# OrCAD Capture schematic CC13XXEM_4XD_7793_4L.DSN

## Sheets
1 CC13xxEM_4XD_7793_4L: size A3; title: CC13xxEM-4XD-7793_4L; rev: 1.0.0
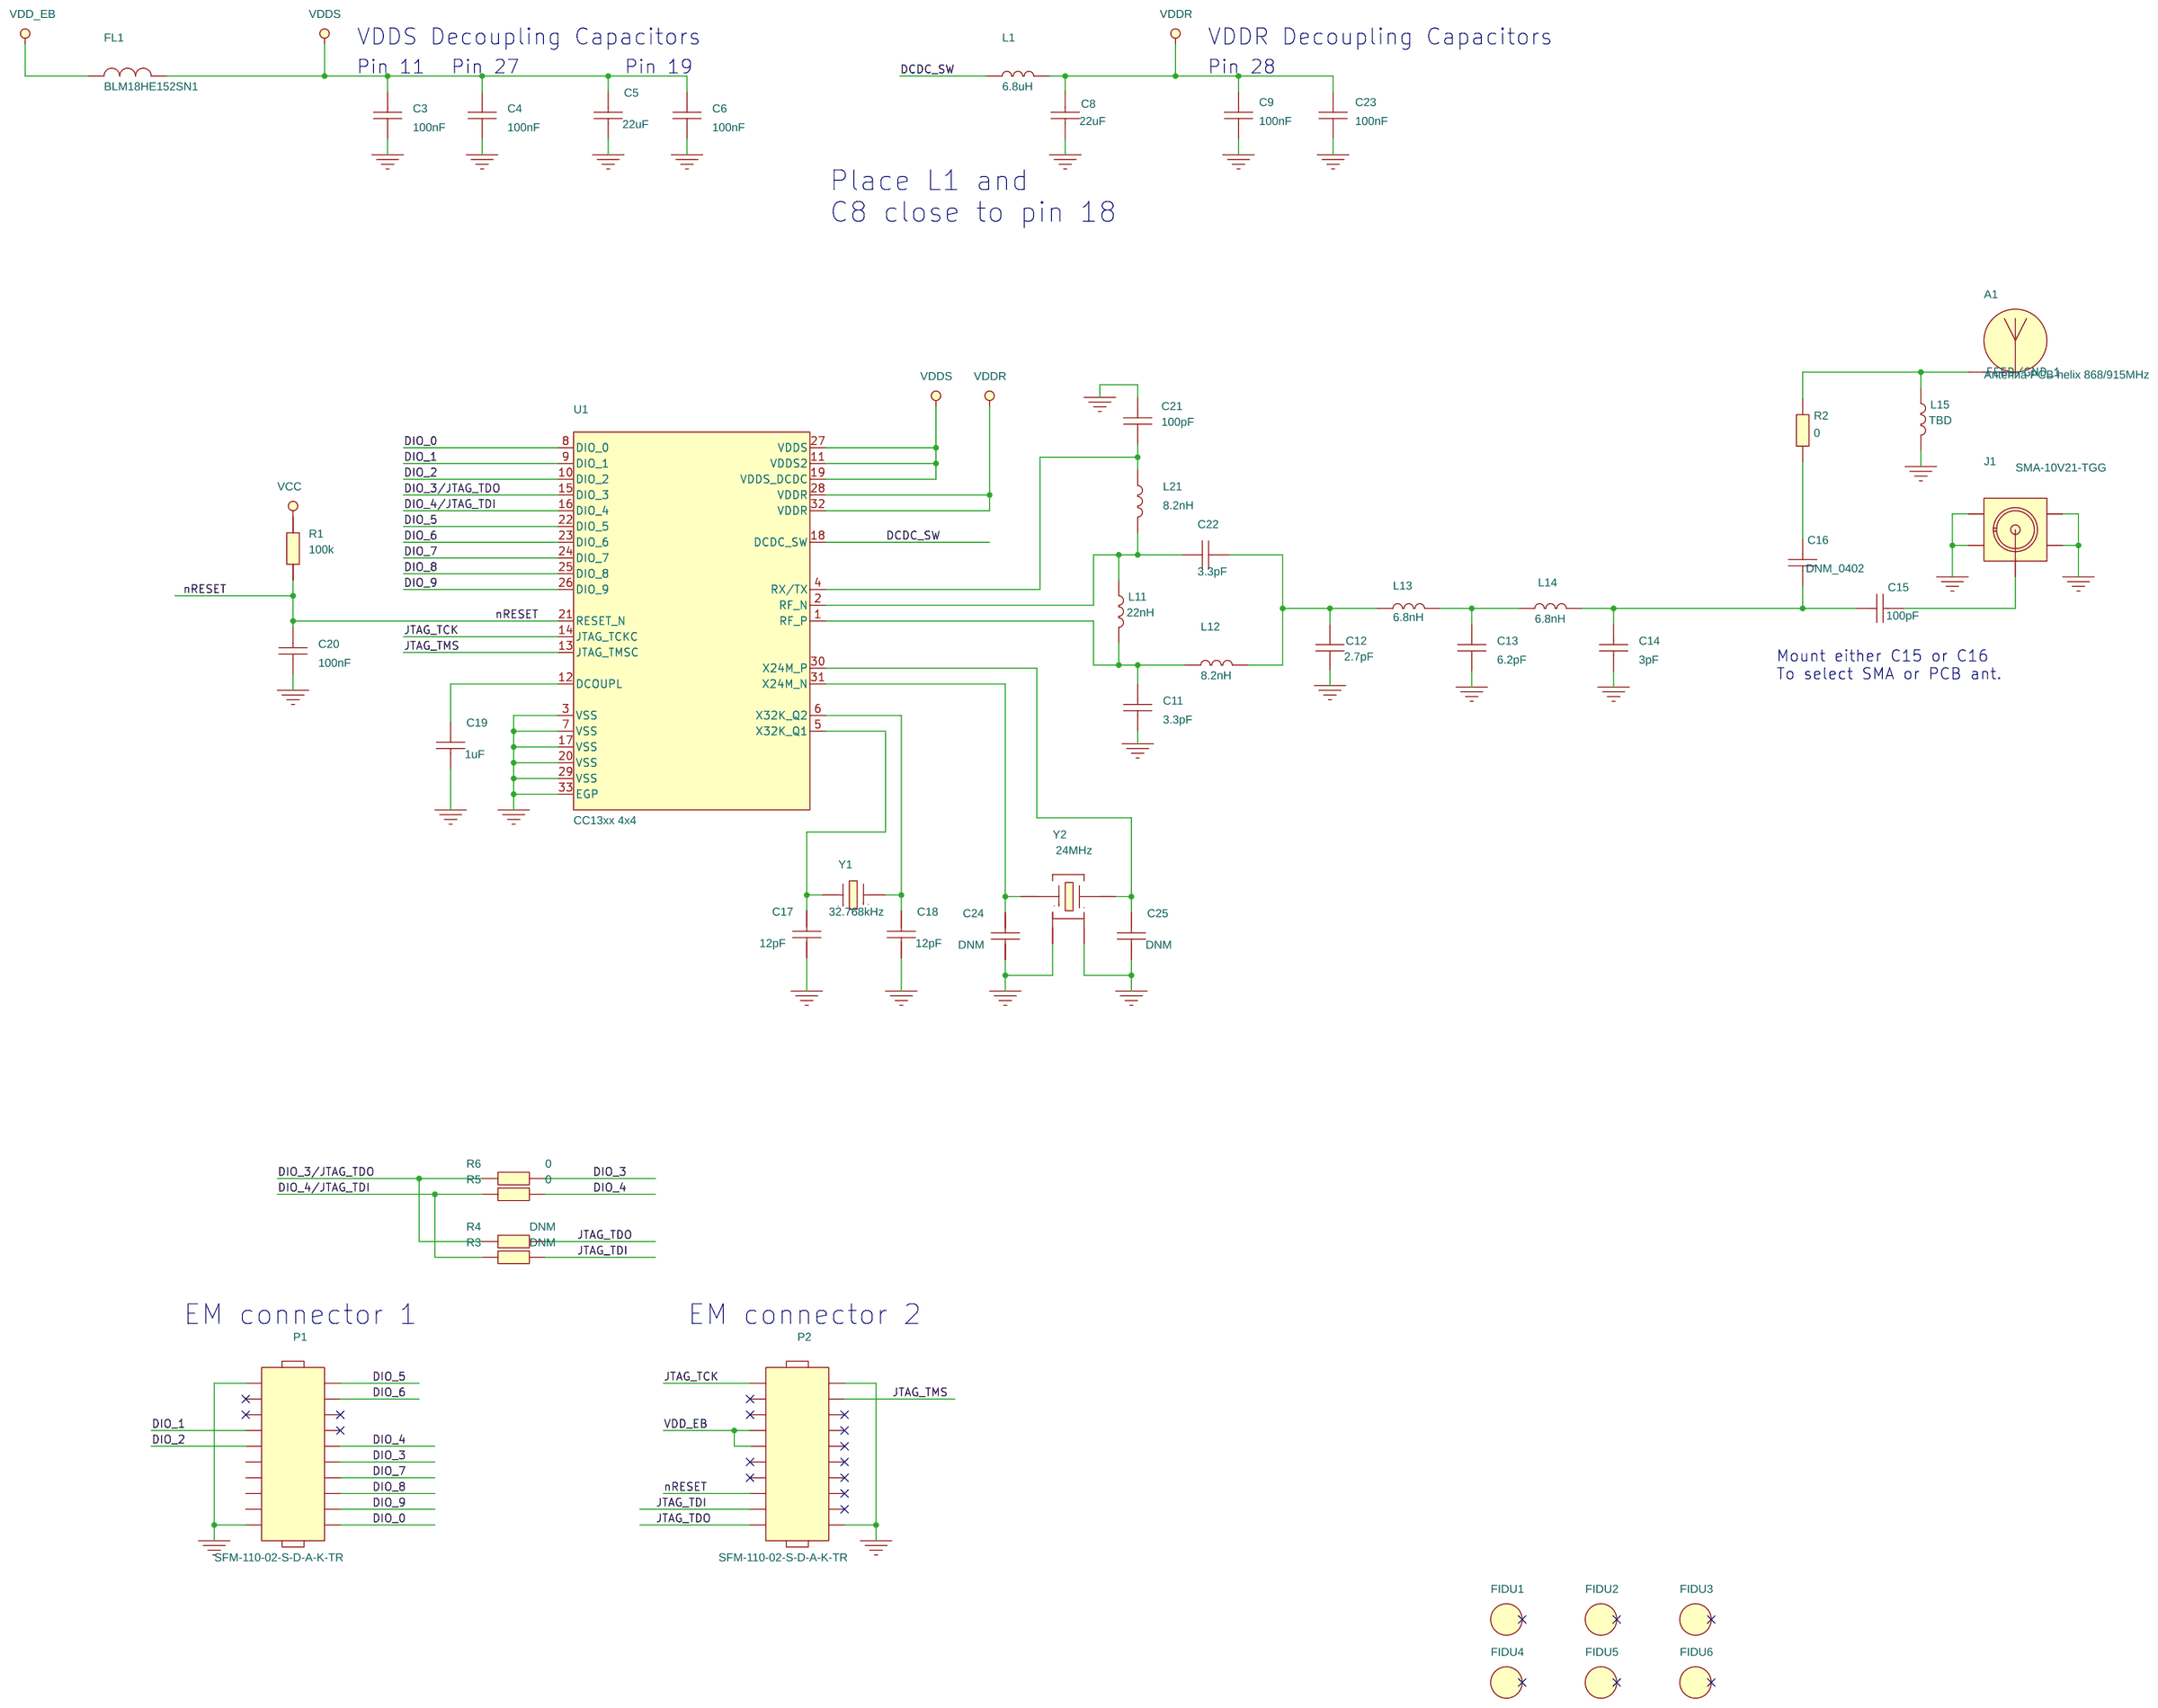
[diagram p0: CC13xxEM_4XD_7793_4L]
2 Revision: title: Revision
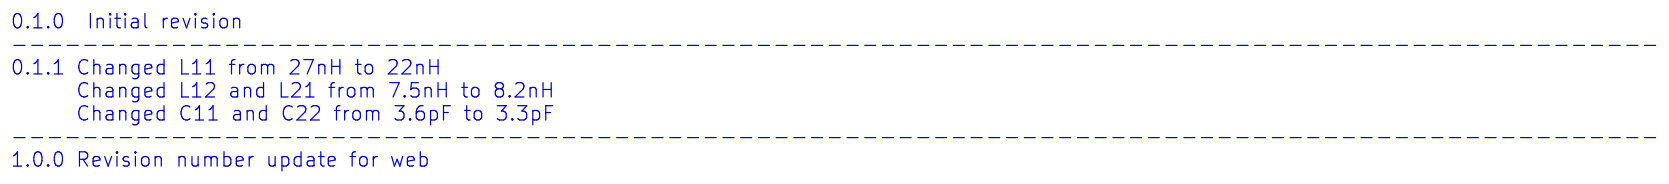
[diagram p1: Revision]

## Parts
A1  Antenna PCB helix 868/915MHz  [Antenna868_915MHz_MIRROR_A2N]
C3  100nF  [CAPC1005X60L]
C4  100nF  [CAPC1005X60L]
C5  22uF  [CAPC1608X100A2L]
C6  100nF  [CAPC1005X60L]
C8  22uF  [CAPC1608X100A2L]
C9  100nF  [CAPC1005X60L]
C11  3.3pF  [CAPC1005X60L]
C12  2.7pF  [CAPC1005X60L]
C13  6.2pF  [CAPC1005X60L]
C14  3pF  [CAPC1005X60L]
C15  100pF  [CAPC1005X60N]
C16  DNM_0402  [CAPC1005X60N]
C17  12pF  [CAPC1005X60L]
C18  12pF  [CAPC1005X60L]
C19  1uF  [CAPC1005X60L]
C20  100nF  [CAPC1005X60L]
C21  100pF  [CAPC1005X60L]
C22  3.3pF  [CAPC1005X60L]
C23  100nF  [CAPC1005X60L]
C24  DNM  [CAPC1005X60L]
C25  DNM  [CAPC1005X60L]
FIDU1  FIDU_1MM  [FID100X115]
FIDU2  FIDU_1MM  [FID100X115]
FIDU3  FIDU_1MM  [FID100X115]
FIDU4  FIDU_1MM  [FID100X115]
FIDU5  FIDU_1MM  [FID100X115]
FIDU6  FIDU_1MM  [FID100X115]
FL1  BLM18HE152SN1  [FIL_BLM18HE152SN1DL]
J1  SMA-10V21-TGG  [HUSTSAN_SMA10V21TGGAN]
L1  6.8uH  [INDC2012X150L]
L11  22nH  [INDC1005X60L]
L12  8.2nH  [INDC1005X60L]
L13  6.8nH  [INDC1005X60L]
L14  6.8nH  [INDC1005X60L]
L15  TBD  [INDC1005X60L]
L21  8.2nH  [INDC1005X60L]
P1  SFM-110-02-S-D-A-K-TR  [SAMTEC_SFM11002AN]
P2  SFM-110-02-S-D-A-K-TR  [SAMTEC_SFM11002AN]
R1  100k  [RESC1005X40L]
R2  0  [RESC1005X40L]
R3  DNM  [RESC1005X40L]
R4  DNM  [RESC1005X40L]
R5  0  [RESC1005X40N]
R6  0  [RESC1005X40N]
U1  CC13xx 4x4  [QFNFC40P400X400X100-33L]
Y1  32.768kHz  [XTAL_FC-135N]
Y2  24MHz  [OSCCC250X320X80-4L]

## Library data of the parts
A1 = ANTENNA: ANTENNA, NON COMPONENT, PCB HELIX 868/915MHz, NOT APPLY; AutoDoc File: http://notefied-dynamic-precision.com/DB/Apps/Desktop/Item/Object.aspx?id=87165; Budget Currency: N/A; Budget Price: N/A; Datasheet URL 1: N/A; Datasheet URL 2: www.ti.com; Definied Quality: COMMERCIAL; Esd Level: N/A; FPLIST: Antenna868_915MHz_A2N,Antenna868_915MHz_MIRROR_A2N,; Frequency: 868/915MHz; Last Time Buy: N/A; Lead Time: N/A; LifeCycle Status: ACTIVE; MPN: ANTENNA PCB HELIX 868/915MHz; MPN Status: ACTIVE; MSL: N/A; MTBF: N/A; MTBF Standard: N/A; Manufacturer: TEXAS INSTRUMENTS; Max Oper Temp: N/A; Min Oper Temp: N/A; Mounting Type: NOT APPLY; NOTE Status: PREFERRED; Old Footprint: Antenna868_915MHz_A2N,Antenna868_915MHz_MIRROR_A2N; Packing Size: 2500; Packing Type: TAPE_&_REEL; Part Number: 13-00397; Part Type: MECHANIC\ANTENNA\NON_COMPONENT; Revision: R003; RoHS Status: ROHS_COMPLIANT; WEIGHT: N/A
C3 C4 C6 C9 C23 = CAPACITOR: CAPACITOR, CERAMIC X7R, 100nF, 6.3V, -10%/+10%, -55DEGC/+125DEGC, 0402, SMD; ALT_SYMBOLS: CAPC1005X60L,CAPC1005X60M; AutoDoc File: http://notefied-dynamic-precision.com/DB/Apps/Desktop/Item/Object.aspx?id=73748; Budget Currency: EUR; Budget Price: 0.007; Datasheet URL 1: http://search.murata.co.jp/Ceramy/image/img/w_hinm/L0005E.pdf; Datasheet URL 2: http://psearch.murata.com/capacitor/product/GRM155R70J104KA01%23.pdf; Definied Quality: INDUSTRIAL; Dielectric Type: X7R; Esd Level: N/A; FPLIST: CAPC1005X60N,CAPC1005X60L,CAPC1005X60M; Last Time Buy: N/A; Lead Time: 14; LifeCycle Status: NRND; MPN: GRM155R70J104KA01D; MPN Status: NRND; MSL: 1; MTBF: N/A; MTBF Standard: N/A; Manufacturer: MURATA; Max Oper Temp: +125DEGC; Max Tol: +10%; Min Oper Temp: -55DEGC; Min Tol: -10%; Mounting Type: SMD; NOTE Status: PREFERRED; Old Footprint: CAPC1005X60N,0402; PCB Package: 0402; Packing Size: 10000; Packing Type: TAPE_&_REEL; Part Number: 02-02323; Part Type: CAPACITOR\CERAMIC\0402; Revision: R000; RoHS Status: ROHS_COMPLIANT; Rtd Voltage: 6.3V; WEIGHT: 0.0016g
C5 C8 = CAPACITOR: CAPACITOR, CERAMIC, X5R, 22uF, 6.3V, -20%/+20%, -55DEGC/+85DEGC, 0603, SMD; ALT_SYMBOLS: CAPC1608X100A2L,CAPC1608X100A2M; AutoDoc File: http://notefied-dynamic-precision.com/DB/Apps/Desktop/Item/Object.aspx?id=104385; Budget Currency: EUR; Budget Price: 0.062; Datasheet URL 1: N/A; Datasheet URL 2: http://psearch.murata.com/capacitor/product/GRM188R60J226MEA0%23.pdf; Definied Quality: INDUSTRIAL; Dielectric Type: X5R; Esd Level: N/A; FPLIST: CAPC1608X100A2N,CAPC1608X100A2L,CAPC1608X100A2M; Last Time Buy: N/A; Lead Time: 26; LifeCycle Status: ACTIVE; MPN: GRM188R60J226MEA0D; MPN Status: ACTIVE; MSL: N/A; MTBF: N/A; MTBF Standard: N/A; Manufacturer: MURATA; Max Oper Temp: +85DEGC; Max Tol: +20%; Min Oper Temp: -55DEGC; Min Tol: -20%; Mounting Type: SMD; NOTE Status: PREFERRED; Old Footprint: CAPC1608X100A2N; PCB Package: 0603; Packing Size: 4000; Packing Type: TAPE_&_REEL; Part Number: 02-07053; Part Type: CAPACITOR\CERAMIC\0603; Revision: R001; RoHS Status: ROHS_COMPLIANT; Rtd Voltage: 6.3V; WEIGHT: 0.0091g
C11 C22 = CAPACITOR: CAPACITOR, CERAMIC C0G/NP0, 3.3pF, 50V, -0.25pF/+0.25pF, -55DEGC/+125DEGC, 0402, SMD; ALT_SYMBOLS: CAPC1005X60L,CAPC1005X60M; AutoDoc File: http://notefied-dynamic-precision.com/DB/Apps/Desktop/Item/Object.aspx?id=86077; Budget Currency: EUR; Budget Price: 0.007; Datasheet URL 1: http://search.murata.co.jp/Ceramy/image/img/w_hinm/L0005E.pdf; Datasheet URL 2: http://psearch.murata.com/capacitor/product/GRM1555C1H3R3CA01%23.pdf; Definied Quality: INDUSTRIAL; Dielectric Type: C0G/NP0; Esd Level: N/A; FPLIST: CAPC1005X60N,CAPC1005X60L,CAPC1005X60M; Last Time Buy: N/A; Lead Time: 12; LifeCycle Status: ACTIVE; MPN: GRM1555C1H3R3CA01D; MPN Status: ACTIVE; MSL: 1; MTBF: N/A; MTBF Standard: N/A; Manufacturer: MURATA; Max Oper Temp: +125DEGC; Max TC: +30PPM/DEGC; Max Tol: +0.25pF; Min Oper Temp: -55DEGC; Min TC: -30PPM/DEGC; Min Tol: -0.25pF; Mounting Type: SMD; NOTE Status: PREFERRED; Old Footprint: CAPC1005X60N; PCB Package: 0402; Packing Size: 10000; Packing Type: TAPE_&_REEL; Part Number: 02-04369; Part Type: CAPACITOR\CERAMIC\0402; Revision: R001; RoHS Status: ROHS_COMPLIANT; Rtd Voltage: 50V; WEIGHT: 0.0016g
C12 = CAPACITOR: CAPACITOR, CERAMIC C0G/NP0, 2.7pF, 50V, -0.25pF/+0.25pF, -55DEGC/+125DEGC, 0402, SMD; ALT_SYMBOLS: CAPC1005X60L,CAPC1005X60M; AutoDoc File: http://notefied-dynamic-precision.com/DB/Apps/Desktop/Item/Object.aspx?id=87809; Budget Currency: EUR; Budget Price: 0.006; Datasheet URL 1: http://search.murata.co.jp/Ceramy/image/img/w_hinm/L0005E.pdf; Datasheet URL 2: http://psearch.murata.com/capacitor/product/GRM1555C1H2R7CA01%23.pdf; Definied Quality: INDUSTRIAL; Dielectric Type: C0G/NP0; Esd Level: N/A; FPLIST: CAPC1005X60N,CAPC1005X60L,CAPC1005X60M; Last Time Buy: N/A; Lead Time: 12; MPN: GRM1555C1H2R7CA01D; MPN Status: ACTIVE; MSL: 1; MTBF: N/A; MTBF Standard: N/A; Manufacturer: MURATA; Max Oper Temp: +125DEGC; Max Tol: +0.25pF; Min Oper Temp: -55DEGC; Min Tol: -0.25pF; Mounting Type: SMD; NOTE Status: PREFERRED; Old Footprint: CAPC1005X60N; PCB Package: 0402; Packing Size: 10000; Packing Type: TAPE_&_REEL; Part Number: 02-04679; Part Type: CAPACITOR\CERAMIC\0402; Revision: R001; RoHS Status: ROHS_COMPLIANT; Rtd Voltage: 50V; WEIGHT: 0.0016g
C13 = CAPACITOR: CAPACITOR, CERAMIC C0G/NP0, 6.2pF, 50V, -0.25pF/+0.25pF, -55DEGC/+125DEGC, 0402, SMD; ALT_SYMBOLS: CAPC1005X60L,CAPC1005X60M; AutoDoc File: http://notefied-dynamic-precision.com/DB/Apps/Desktop/Item/Object.aspx?id=87255; Budget Currency: EUR; Budget Price: 0.006; Datasheet URL 1: http://search.murata.co.jp/Ceramy/image/img/w_hinm/L0005E.pdf; Datasheet URL 2: http://psearch.murata.com/capacitor/product/GRM1555C1H6R2CA01%23.pdf; Definied Quality: INDUSTRIAL; Dielectric Type: C0G/NP0; Esd Level: N/A; FPLIST: CAPC1005X60N,CAPC1005X60L,CAPC1005X60M; Last Time Buy: N/A; Lead Time: 10; MPN: GRM1555C1H6R2CA01D; MPN Status: ACTIVE; MSL: 1; MTBF: N/A; MTBF Standard: N/A; Manufacturer: MURATA; Max Oper Temp: +125DEGC; Max Tol: +0.25pF; Min Oper Temp: -55DEGC; Min Tol: -0.25pF; Mounting Type: SMD; NOTE Status: PREFERRED; Old Footprint: CAPC1005X60N; PCB Package: 0402; Packing Size: 10000; Packing Type: TAPE_&_REEL; Part Number: 02-04608; Part Type: CAPACITOR\CERAMIC\0402; Revision: R001; RoHS Status: ROHS_COMPLIANT; Rtd Voltage: 50V; WEIGHT: 0.0016g
C14 = CAPACITOR: CAPACITOR, CERAMIC C0G/NP0, 3pF, 50V, -0.25pF/+0.25pF, -55DEGC/+125DEGC, 0402, SMD; ALT_SYMBOLS: CAPC1005X60L,CAPC1005X60M; AutoDoc File: http://notefied-dynamic-precision.com/DB/Apps/Desktop/Item/Object.aspx?id=87252; Budget Currency: EUR; Budget Price: 0.006; Datasheet URL 1: http://search.murata.co.jp/Ceramy/image/img/w_hinm/L0005E.pdf; Datasheet URL 2: http://psearch.murata.com/capacitor/product/GRM1555C1H3R0CA01%23.pdf; Definied Quality: INDUSTRIAL; Dielectric Type: C0G/NP0; Esd Level: N/A; FPLIST: CAPC1005X60N,CAPC1005X60L,CAPC1005X60M; Last Time Buy: N/A; Lead Time: 16; LifeCycle Status: ACTIVE; MPN: GRM1555C1H3R0CA01D; MPN Status: ACTIVE; MSL: 1; MTBF: N/A; MTBF Standard: N/A; Manufacturer: MURATA; Max Oper Temp: +125DEGC; Max Tol: +0.25pF; Min Oper Temp: -55DEGC; Min Tol: -0.25pF; Mounting Type: SMD; NOTE Status: PREFERRED; Old Footprint: CAPC1005X60N; PCB Package: 0402; Packing Size: 10000; Packing Type: TAPE_&_REEL; Part Number: 02-04606; Part Type: CAPACITOR\CERAMIC\0402; Revision: R001; RoHS Status: ROHS_COMPLIANT; Rtd Voltage: 50V; WEIGHT: 0.0016g
C15 = CAPACITOR: CAPACITOR, CERAMIC C0G/NP0, 100pF, 50V, -5%/+5%, -55DEGC/+125DEGC, 0402, SMD; ALT_SYMBOLS: CAPC1005X60L,CAPC1005X60M; AutoDoc File: http://notefied-dynamic-precision.com/DB/Apps/Desktop/Item/Object.aspx?id=86072; Budget Currency: EUR; Budget Price: 0.004; Datasheet URL 1: http://search.murata.co.jp/Ceramy/image/img/w_hinm/L0005E.pdf; Datasheet URL 2: http://psearch.murata.com/capacitor/product/GRM1555C1H101JA01%23.pdf; Definied Quality: INDUSTRIAL; Dielectric Type: C0G/NP0; Esd Level: N/A; FPLIST: CAPC1005X60N,CAPC1005X60L,CAPC1005X60M; Last Time Buy: N/A; Lead Time: 12; LifeCycle Status: ACTIVE; MPN: GRM1555C1H101JA01D; MPN Status: ACTIVE; MSL: 1; MTBF: N/A; MTBF Standard: N/A; Manufacturer: MURATA; Max Oper Temp: +125DEGC; Max Tol: +5%; Min Oper Temp: -55DEGC; Min Tol: -5%; Mounting Type: SMD; NOTE Status: PREFERRED; PCB Package: 0402; Packing Size: 10000; Packing Type: TAPE_&_REEL; Part Number: 02-04365; Part Type: CAPACITOR\CERAMIC\0402; Revision: R002; RoHS Status: ROHS_COMPLIANT; Rtd Voltage: 50V; WEIGHT: 0.0016g
C16 = CAPACITOR: CAPACITOR, CERAMIC, N/A VALUE, -55DEGC/+125DEGC, 0402, SMD; ALT_SYMBOLS: CAPC1005X60L,CAPC1005X60M; AutoDoc File: http://notefied-dynamic-precision.com/DB/Apps/Desktop/Item/Object.aspx?id=84862; Budget Currency: USD; Budget Price: 0.00589; Datasheet URL 1: N/A; Datasheet URL 2: N/A; Definied Quality: INDUSTRIAL; Esd Level: N/A; FPLIST: CAPC1005X60N,CAPC1005X60L,CAPC1005X60M; Last Time Buy: N/A; Lead Time: N/A; LifeCycle Status: ACTIVE; MPN: CAPACITOR_0402_DNM_N/A_M; MPN Status: ACTIVE; MSL: N/A; MTBF: N/A; MTBF Standard: N/A; Manufacturer: MANUFACTURER SELECTION; Max Oper Temp: +125DEGC; Min Oper Temp: -55DEGC; Mounting Type: SMD; NOTE Status: PREFERRED; PCB Package: 0402; Packing Size: 10000; Packing Type: TAPE_&_REEL; Part Number: 02-04164; Part Type: CAPACITOR\CERAMIC\0402; Revision: R000; RoHS Status: MISSING_INFO; WEIGHT: N/A
C17 C18 = CAPACITOR: CAPACITOR, CERAMIC C0G/NP0, 12pF, 50V, -5%/+5%, -55DEGC/+125DEGC, 0402, SMD; ALT_SYMBOLS: CAPC1005X60L,CAPC1005X60M; AutoDoc File: http://notefied-dynamic-precision.com/DB/Apps/Desktop/Item/Object.aspx?id=80123; Budget Currency: USD; Budget Price: 0.00589; Datasheet URL 1: N/A; Datasheet URL 2: N/A; Definied Quality: INDUSTRIAL; Dielectric Type: C0G/NP0; Esd Level: N/A; FPLIST: CAPC1005X60N,CAPC1005X60L,CAPC1005X60M; Last Time Buy: N/A; Lead Time: N/A; LifeCycle Status: ACTIVE; MPN: CAPACITOR_0402_12pF_C0G/NP0_M_+/-5%_50V; MPN Status: ACTIVE; MSL: N/A; MTBF: N/A; MTBF Standard: N/A; Manufacturer: MANUFACTURER SELECTION; Max Oper Temp: +125DEGC; Max Tol: +5%; Min Oper Temp: -55DEGC; Min Tol: -5%; Mounting Type: SMD; NOTE Status: PREFERRED; Old Footprint: CAPC1005X60N; PCB Package: 0402; Packing Size: 10000; Packing Type: TAPE_&_REEL; Part Number: 02-03030; Part Type: CAPACITOR\CERAMIC\0402; Revision: R000; RoHS Status: ROHS_COMPLIANT; Rtd Voltage: 50V; WEIGHT: N/A
C19 = CAPACITOR: CAPACITOR, CERAMIC X5R, 1uF, 10V, -10%/+10%, -55DEGC/+85DEGC, 0402, SMD; ALT_SYMBOLS: CAPC1005X60L,CAPC1005X60M; AutoDoc File: http://notefied-dynamic-precision.com/DB/Apps/Desktop/Item/Object.aspx?id=74236; Budget Currency: EUR; Budget Price: 0.015; Datasheet URL 1: http://search.murata.co.jp/Ceramy/image/img/w_hinm/L0005E.pdf; Datasheet URL 2: http://psearch.murata.com/capacitor/product/GRM155R61A105KE15%23.pdf; Definied Quality: INDUSTRIAL; Dielectric Type: X5R; Esd Level: N/A; FPLIST: CAPC1005X60N,CAPC1005X60L,CAPC1005X60M; Last Time Buy: N/A; Lead Time: 14; MPN: GRM155R61A105KE15D; MPN Status: ACTIVE; MSL: 1; MTBF: N/A; MTBF Standard: N/A; Manufacturer: MURATA; Max Oper Temp: +85DEGC; Max Tol: +10%; Min Oper Temp: -55DEGC; Min Tol: -10%; Mounting Type: SMD; NOTE Status: PREFERRED; Old Footprint: CAPC1005X60N,0402; PCB Package: 0402; Packing Size: 10000; Packing Type: TAPE_&_REEL; Part Number: 02-02381; Part Type: CAPACITOR\CERAMIC\0402; Revision: R002; RoHS Status: ROHS_COMPLIANT; Rtd Voltage: 10V; WEIGHT: 0.0016g
C20 = CAPACITOR: CAPACITOR, CERAMIC X7R, 100nF, 6.3V, -10%/+10%, -55DEGC/+125DEGC, 0402, SMD; ALT_SYMBOLS: CAPC1005X60L,CAPC1005X60M; AutoDoc File: http://notefied-dynamic-precision.com/DB/Apps/Desktop/Item/Object.aspx?id=73748; Budget Currency: EUR; Budget Price: 0.003; Datasheet URL 1: http://search.murata.co.jp/Ceramy/image/img/A01X/G101/ENG/GRM155R70J104KA01-01.pdf; Datasheet URL 2: http://search.murata.co.jp/Ceramy/image/img/A01X/G101/ENG/GRM155R70J104KA01-01.pdf; Dielectric Type: X7R; FPLIST: CAPC1005X60N,CAPC1005X60L,CAPC1005X60M; Lead Time: 10; LifeCycle Status: ACTIVE; MPN: GRM155R70J104KA01D; MPN Status: ACTIVE; Manufacturer: MURATA; Max Oper Temp: +125DEGC; Max Tol: +10%; Min Oper Temp: -55DEGC; Min Tol: -10%; Mounting Type: SMD; NOTE Status: PREFERRED; Old Footprint: CAPC1005X60N,0402; PCB Package: 0402; Packing Size: 10000; Packing Type: TAPE_&_REEL; Part Number: 02-02323; Part Type: CAPACITOR\CERAMIC\0402; Revision: R000; RoHS Status: ROHS_COMPLIANT; Rtd Voltage: 6.3V; WEIGHT: 0.0016g
C21 = CAPACITOR: CAPACITOR, CERAMIC C0G/NP0, 100pF, 50V, -5%/+5%, -55DEGC/+125DEGC, 0402, SMD; ALT_SYMBOLS: CAPC1005X60L,CAPC1005X60M; AutoDoc File: http://notefied-dynamic-precision.com/DB/Apps/Desktop/Item/Object.aspx?id=86072; Budget Currency: EUR; Budget Price: 0.006; Datasheet URL 1: http://search.murata.co.jp/Ceramy/image/img/w_hinm/L0005E.pdf; Datasheet URL 2: http://psearch.murata.com/capacitor/product/GRM1555C1H101JA01%23.pdf; Definied Quality: INDUSTRIAL; Dielectric Type: C0G/NP0; Esd Level: N/A; FPLIST: CAPC1005X60N,CAPC1005X60L,CAPC1005X60M; Last Time Buy: N/A; Lead Time: 12; MPN: GRM1555C1H101JA01D; MPN Status: ACTIVE; MSL: 1; MTBF: N/A; MTBF Standard: N/A; Manufacturer: MURATA; Max Oper Temp: +125DEGC; Max TC: +30PPM/DEGC; Max Tol: +5%; Min Oper Temp: -55DEGC; Min TC: -30PPM/DEGC; Min Tol: -5%; Mounting Type: SMD; NOTE Status: PREFERRED; Old Footprint: CAPC1005X60N; PCB Package: 0402; Packing Size: 10000; Packing Type: TAPE_&_REEL; Part Number: 02-04365; Part Type: CAPACITOR\CERAMIC\0402; Revision: R002; RoHS Status: ROHS_COMPLIANT; Rtd Voltage: 50V; WEIGHT: 0.0016g
C24 C25 = CAPACITOR: CAPACITOR, CERAMIC, N/A VALUE, -55DEGC/+125DEGC, 0402, SMD; ALT_SYMBOLS: CAPC1005X60L,CAPC1005X60M; AutoDoc File: http://notefied-dynamic-precision.com/DB/Apps/Desktop/Item/Object.aspx?id=84862; Budget Currency: USD; Budget Price: 0.00589; FPLIST: CAPC1005X60N,CAPC1005X60L,CAPC1005X60M; MPN: CAPACITOR_0402_DNM_N/A_M; MPN Status: ACTIVE; Manufacturer: Manufacturer selection; Max Oper Temp: +125DEGC; Min Oper Temp: -55DEGC; Mounting Type: SMD; NOTE Status: PREFERRED; Old Footprint: CAPC1005X60N; PCB Package: 0402; Packing Size: 10000; Packing Type: TAPE_&_REEL; Part Number: 02-04164; Part Type: CAPACITOR\CERAMIC\0402; Revision: R000; RoHS Status: PART NOT KNOWN
FIDU1-FIDU6 = FIDMARK: FIDUCIAL MARK, ROUND 1MM; AutoDoc File: https://notefied-dynamic-precision.com/NotefiedWebServices/AutoDocs.aspx?itemid=74548; Part Number: 19-00111; Part Type: NON_COMPONENT\FIDUCIAL; Revision: R001
FL1 = FILTER_2PIN: FILTER, EMI, 1500@100MHz, -55DEGC/+125DEGC, 0603, SMD; ALT_SYMBOLS: FIL_BLM18HE152SN1DL,FIL_BLM18HE152SN1DM; AutoDoc File: http://notefied-dynamic-precision.com/DB/Apps/Desktop/Item/Object.aspx?id=85575; Budget Currency: EUR; Budget Price: 0.085; Datasheet URL 1: http://search.murata.co.jp/Ceramy/image/img/PDF/ENG/L0110S0101BLM18H.pdf; Datasheet URL 2: http://search.murata.co.jp/Ceramy/image/img/PDF/ENG/L0110S0101BLM18H.pdf; FPLIST: FIL_BLM18HE152SN1DN,FIL_BLM18HE152SN1DL,FIL_BLM18HE152SN1DM; Impedance: 1500@100MHz; Lead Time: 26; MPN: BLM18HE152SN1D; MPN Status: ACTIVE; Manufacturer: MURATA; Max Oper Temp: +125DEGC; Max Tol: +25%; Min Oper Temp: -55DEGC; Min Tol: -25%; Mounting Type: SMD; NOTE Status: PREFERRED; Old Footprint: FIL_BLM18HE152SN1DN; PCB Package: 0603; Packing Size: 4000; Packing Type: TAPE_&_REEL; Part Number: 04-00470; Part Type: FILTER\EMI\0603; Revision: R001; RoHS Status: ROHS_COMPLIANT; Rtd Current: 0.5A; WEIGHT: 0.006g
J1 = CONN_COAX_1+4: CONNECTOR, COAX RF, STRAIGHT, FEMALE, 1 PIN, SMD; ALT_SYMBOLS: HUSTSAN_SMA10V21TGGL,HUSTSAN_SMA10V21TGGM; AutoDoc File: http://notefied-dynamic-precision.com/DB/Apps/Desktop/Item/Object.aspx?id=84956; Budget Currency: USD; Budget Price: 1.21; Datasheet URL 1: http://www.hustsan.com.tw/uploaddir/product/SMA-10V21.pdf; Datasheet URL 2: http://www.hustsan.com.tw/uploaddir/product/SMA-10V21.pdf; FPLIST: HUSTSAN_SMA10V21TGGAN,HUSTSAN_SMA10V21TGGN; Lead Time: 5; MPN Status: ACTIVE; MSL: N/A; Manufacturer: HUS-TSAN; Mounting Type: SMD; NOTE Status: PREFERRED; No Of Pos: 1; Old Footprint: HUSTSAN_SMA10V21TGGAN,HUSTSAN_SMA10V21TGGN; Packing Size: 350; Packing Type: TAPE_&_REEL; Part Number: 06-02188; Part Type: CONNECTOR\COAX; Revision: R003; RoHS Status: N/A; WEIGHT: N/A
L1 = INDUCTOR: INDUCTOR, CHIP, FERRITE CORE, 6.8uH, -20%/+20%, IR:1.1A, -55DEGC/+125DEGC, 0805, SMD; ALT_SYMBOLS: INDC2012X150L,INDC2012X150M; AutoDoc File: http://notefied-dynamic-precision.com/DB/Apps/Desktop/Item/Object.aspx?id=102853; Datasheet URL 1: N/A; Datasheet URL 2: http://product.tdk.com/inductor/ind/detailed_information.php?lang=en&ref=us&part_no=MLZ2012N6R8LT000; FPLIST: INDC2012X150N,INDC2012X150L,INDC2012X150M; Last Time Buy: N/A; LifeCycle Status: ACTIVE; MPN: MLZ2012N6R8LT000; MPN Status: ACTIVE; Manufacturer: TDK; Max Oper Temp: +125DEGC; Max Tol: +20%; Min Oper Temp: -55DEGC; Min Tol: -20%; Mounting Type: SMD; NOTE Status: PREFERRED; Old Footprint: INDC2012X150N; PCB Package: 0805; Packing Size: 4000; Packing Type: TAPE_&_REEL; Part Number: 03-07266; Part Type: INDUCTOR\CHIP\0805; Resistance: 0.25; Revision: R001; RoHS Status: ROHS_COMPLIANT; Rtd Current: 1.1A; WEIGHT: 0.01g
L11 = INDUCTOR: INDUCTOR, RF, CHIP, NON-MAGNETIC CORE, 22nH, -5%/+5%, 0.3A, -55DEGC/+125DEGC, 0402, SMD; ALT_SYMBOLS: INDC1005X60M,INDC1005X60L; AutoDoc File: http://notefied-dynamic-precision.com/DB/Apps/Desktop/Item/Object.aspx?id=85868; Budget Currency: EUR; Budget Price: 0.03; Datasheet URL 1: N/A; Datasheet URL 2: http://psearch.murata.com/inductor/product/LQG15HS22NJ02%23.pdf; Definied Quality: INDUSTRIAL; Esd Level: N/A; FPLIST: INDC1005X60N,INDC1005X60M,INDC1005X60L; Frequency: 1900MHz; Last Time Buy: N/A; Lead Time: 9; LifeCycle Status: ACTIVE; MPN: LQG15HS22NJ02D; MPN Status: ACTIVE; MSL: N/A; MTBF: N/A; MTBF Standard: N/A; Manufacturer: MURATA; Max Oper Temp: +125DEGC; Max Tol: +5%; Min Oper Temp: -55DEGC; Min Tol: -5%; Mounting Type: SMD; NOTE Status: PREFERRED; Old Footprint: INDC1005X60N; PCB Package: 0402; Packing Size: 10000; Packing Type: TAPE_&_REEL; Part Number: 03-06537; Part Type: INDUCTOR\RF\CHIP\0402; Revision: R001; RoHS Status: ROHS_COMPLIANT; Rtd Current: 0.3A; WEIGHT: 0.001g
L12 L21 = INDUCTOR: INDUCTOR, RF, CHIP, NON-MAGNETIC CORE, 8.2nH, -5%/+5%, 0.3A, -55DEGC/+125DEGC, 0402, SMD; ALT_SYMBOLS: INDC1005X60L,INDC1005X60M; AutoDoc File: http://notefied-dynamic-precision.com/DB/Apps/Desktop/Item/Object.aspx?id=87738; Budget Currency: EUR; Budget Price: 0.031; Datasheet URL 1: N/A; Datasheet URL 2: http://psearch.murata.com/inductor/product/LQG15HS8N2J02%23.pdf; Definied Quality: INDUSTRIAL; Esd Level: N/A; FPLIST: INDC1005X60N,INDC1005X60L,INDC1005X60M; Frequency: 3.7GHz; Last Time Buy: N/A; Lead Time: 9; LifeCycle Status: ACTIVE; MPN: LQG15HS8N2J02D; MPN Status: ACTIVE; MSL: N/A; MTBF: N/A; MTBF Standard: N/A; Manufacturer: MURATA; Max Oper Temp: +125DEGC; Max Tol: +5%; Min Oper Temp: -55DEGC; Min Tol: -5%; Mounting Type: SMD; NOTE Status: PREFERRED; Old Footprint: INDC1005X60N; PCB Package: 0402; Packing Size: 10000; Packing Type: TAPE_&_REEL; Part Number: 03-06634; Part Type: INDUCTOR\RF\CHIP\0402; Resistance: 0.24; Revision: R001; RoHS Status: ROHS_COMPLIANT; Rtd Current: 0.3A; WEIGHT: 0.001g
L13 L14 = INDUCTOR: INDUCTOR, CHIP, 6.8nH, -5%/+5%, 0.3A, -55DEGC/+125DEGC, 0402, SMD; ALT_SYMBOLS: INDC1005X60L,INDC1005X60M; AutoDoc File: http://notefied-dynamic-precision.com/DB/Apps/Desktop/Item/Object.aspx?id=87737; Budget Currency: EUR; Budget Price: 0.03; Datasheet URL 1: N/A; Datasheet URL 2: http://psearch.murata.com/inductor/product/LQG15HS6N8J02%23.pdf; Definied Quality: INDUSTRIAL; Esd Level: N/A; FPLIST: INDC1005X60N,INDC1005X60L,INDC1005X60M; Frequency: 4.5GHz; Last Time Buy: N/A; Lead Time: 9; LifeCycle Status: ACTIVE; MPN: LQG15HS6N8J02D; MPN Status: ACTIVE; MSL: N/A; MTBF: N/A; MTBF Standard: N/A; Manufacturer: MURATA; Max Oper Temp: +125DEGC; Max Tol: +5%; Min Oper Temp: -55DEGC; Min Tol: -5%; Mounting Type: SMD; NOTE Status: PREFERRED; Old Footprint: INDC1005X60N; PCB Package: 0402; Packing Size: 10000; Packing Type: TAPE_&_REEL; Part Number: 03-06633; Part Type: INDUCTOR\CHIP\0402; Resistance: 0.24; Revision: R001; RoHS Status: ROHS_COMPLIANT; Rtd Current: 0.3A; WEIGHT: 0.001g
L15 = INDUCTOR: INDUCTOR, TO BE DECIDED, 0402, SMD; ALT_SYMBOLS: INDC1005X60M,INDC1005X60L; AutoDoc File: http://notefied-dynamic-precision.com/DB/Apps/Desktop/Item/Object.aspx?id=45714; Budget Currency: N/A; Budget Price: N/A; Datasheet URL 1: N/A; Datasheet URL 2: N/A; Definied Quality: COMMERCIAL; Esd Level: N/A; FPLIST: INDC1005X60N,INDC1005X60M,INDC1005X60L; Last Time Buy: N/A; Lead Time: N/A; LifeCycle Status: ACTIVE; MPN: IND_TBD_0402; MPN Status: ACTIVE; MSL: N/A; MTBF: N/A; MTBF Standard: N/A; Manufacturer: MANUFACTURER SELECTION; Mounting Type: SMD; NOTE Status: PREFERRED; Old Footprint: 0402; Packing Size: N/A; Packing Type: N/A; Part Number: 03-01022; Part Type: INDUCTOR\CHIP\0402; Revision: R002; RoHS Status: ROHS_COMPLIANT; WEIGHT: N/A
P1 P2 = CONN_HEADER_2X10_P_S: CONNECTOR, HEADER, FEMALE, STRAIGHT, 2 ROWS, 20 PINS, PITCH 1.27mm, SMD; Alt IPC Footprints: SAMTEC_SFM11002AL,SAMTEC_SFM11002AM; AutoDoc File: https://notefied-dynamic-precision.com/NotefiedWebServices/AutoDocs.aspx?itemid=85603; Datasheet URL 1: http://www.samtec.com/ProductInformation/TechnicalSpecifications/CatalogPages.aspx?series=SFM; Datasheet URL 2: http://www.samtec.com/documents/webfiles/cpdf/SFM-1XX-XX-XX-S-XX-MKT1.pdf; MPN: SFM-110-02-SM-D-A-K-TR; MPN Status: ACTIVE; Manufacturer: SAMTEC; Max Oper Temp: +125DEGC; Min Oper Temp: -55DEGC; Mounting Type: SMD; NOTE Status: PREFERRED; No Of Pos: 20; No Of Rows: 2; Packing Size: 125; Packing Type: TAPE_&_REEL; Part Number: 06-02251; Part Type: CONNECTOR\HEADER; Pitch: 1.27mm; Revision: R001; RoHS Status: ROHS_COMPLIANT
R1 = RESISTOR: RESISTOR, THICK FILM, 100k, -1%/+1%, 0.063W, 50V, -55DEGC/+155DEGC, 0402, SMD; ALT_SYMBOLS: RESC1005X40L,RESC1005X40M; AutoDoc File: http://notefied-dynamic-precision.com/DB/Apps/Desktop/Item/Object.aspx?id=76892; Budget Currency: USD; Budget Price: 0.00244; Datasheet URL 1: N/A; Datasheet URL 2: N/A; Definied Quality: INDUSTRIAL; Esd Level: N/A; FPLIST: RESC1005X40N,RESC1005X40L,RESC1005X40M; Last Time Buy: N/A; Lead Time: N/A; LifeCycle Status: ACTIVE; MPN: RESISTOR_0402_100k_+/-1%_50V_0.063W_M_+/-100PPM; MPN Status: ACTIVE; MSL: N/A; MTBF: N/A; MTBF Standard: N/A; Manufacturer: MANUFACTURER SELECTION; Max Oper Temp: +155DEGC; Max TC: +100PPM/DEGC; Max Tol: +1%; Min Oper Temp: -55DEGC; Min TC: -100PPM/DEGC; Min Tol: -1%; Mounting Type: SMD; NOTE Status: PREFERRED; Old Footprint: RESC1005X40N; PCB Package: 0402; Packing Size: 10000; Packing Type: TAPE_&_REEL; Part Number: 01-12837; Part Type: RESISTOR\0402\PRECISION; Resistor Type: THICK FILM; Revision: R002; RoHS Status: ROHS_COMPLIANT; Rtd Power: 0.063W; Rtd Voltage: 50V; WEIGHT: N/A
R2 = RESISTOR: RESISTOR, THICK FILM, 0, -5%/+5%, 0.063W, 50V, -55DEGC/+155DEGC, 0402, SMD; ALT_SYMBOLS: RESC1005X40L,RESC1005X40M; AutoDoc File: http://notefied-dynamic-precision.com/DB/Apps/Desktop/Item/Object.aspx?id=75642; Budget Currency: USD; Budget Price: 0.00244; Datasheet URL 1: N/A; Datasheet URL 2: N/A; Definied Quality: INDUSTRIAL; Esd Level: N/A; FPLIST: RESC1005X40N,RESC1005X40L,RESC1005X40M; Last Time Buy: N/A; Lead Time: N/A; LifeCycle Status: ACTIVE; MPN: RESISTOR_0402_0_+/-5%_50V_0.063W_M_+/-200ppm; MPN Status: ACTIVE; MSL: N/A; MTBF: N/A; MTBF Standard: N/A; Manufacturer: MANUFACTURER SELECTION; Max Oper Temp: +155DEGC; Max TC: +200PPM/DEGC; Max Tol: N/A; Min Oper Temp: -55DEGC; Min TC: -200PPM/DEGC; Min Tol: N/A; Mounting Type: SMD; NOTE Status: PREFERRED; Old Footprint: RESC1005X40N; PCB Package: 0402; Packing Size: 10000; Packing Type: TAPE_&_REEL; Part Number: 01-11587; Part Type: RESISTOR\0402\JUMPER; Resistor Type: THICK FILM; Revision: R001; RoHS Status: ROHS_COMPLIANT; Rtd Current: N/A; Rtd Power: 0.063W; Rtd Voltage: 50V; WEIGHT: N/A
R3 R4 = RESISTOR: RESISTOR, DO NOT MOUNT, 0402, SMD; ALT_SYMBOLS: RESC1005X40L,RESC1005X40M; AutoDoc File: http://notefied-dynamic-precision.com/DB/Apps/Desktop/Item/Object.aspx?id=48356; Budget Currency: N/A; Budget Price: N/A; Datasheet URL 1: N/A; Datasheet URL 2: N/A; Definied Quality: N/A; Esd Level: N/A; FPLIST: RESC1005X40N,RESC1005X40L,RESC1005X40M; Last Time Buy: N/A; Lead Time: N/A; MPN Status: ACTIVE; MSL: N/A; MTBF: N/A; MTBF Standard: N/A; Manufacturer: DO NOT MOUNT; Max Oper Temp: N/A; Min Oper Temp: N/A; Mounting Type: SMD; NOTE Status: PREFERRED; Old Footprint: RESC1005X40N,0402; PCB Package: 0402; Packing Size: N/A; Packing Type: N/A; Part Number: 01-02472; Part Type: RESISTOR\0402; Revision: R002; RoHS Status: PART NOT KNOWN; WEIGHT: N/A
R5 R6 = RESISTOR: RESISTOR, THICK FILM, 0, -5%/+5%, 0.063W, 50V, -55DEGC/+155DEGC, 0402, SMD; ALT_SYMBOLS: RESC1005X40L,RESC1005X40M; AutoDoc File: http://notefied-dynamic-precision.com/DB/Apps/Desktop/Item/Object.aspx?id=75642; Budget Currency: USD; Budget Price: 0.00244; Datasheet URL 1: N/A; Datasheet URL 2: N/A; Definied Quality: INDUSTRIAL; Esd Level: N/A; FPLIST: RESC1005X40N,RESC1005X40L,RESC1005X40M; Last Time Buy: N/A; Lead Time: N/A; LifeCycle Status: ACTIVE; MPN: RESISTOR_0402_0_+/-5%_50V_0.063W_M_+/-200ppm; MPN Status: ACTIVE; MSL: N/A; MTBF: N/A; MTBF Standard: N/A; Manufacturer: MANUFACTURER SELECTION; Max Oper Temp: +155DEGC; Max TC: +200PPM/DEGC; Max Tol: N/A; Min Oper Temp: -55DEGC; Min TC: -200PPM/DEGC; Min Tol: N/A; Mounting Type: SMD; NOTE Status: PREFERRED; PCB Package: 0402; Packing Size: 10000; Packing Type: TAPE_&_REEL; Part Number: 01-11587; Part Type: RESISTOR\0402\JUMPER; Resistor Type: THICK FILM; Revision: R001; RoHS Status: ROHS_COMPLIANT; Rtd Current: N/A; Rtd Power: 0.063W; Rtd Voltage: 50V; WEIGHT: N/A
U1 = IC_RF_CC13XX_4X4_QFN32: IC, ANALOG, CUSTOM, CC13xx 4x4, QFN32, SMD; ALT_SYMBOLS: QFNFC40P400X400X100-33L,QFNFC40P400X400X100-33M; AutoDoc File: http://notefied-dynamic-precision.com/DB/Apps/Desktop/Item/Object.aspx?id=90624; Budget Currency: N/A; Budget Price: N/A; Datasheet URL 1: N/A; Datasheet URL 2: www.ti.com; Definied Quality: COMMERCIAL; Esd Level: N/A; FPLIST: QFNFC40P400X400X100-33N,QFNFC40P400X400X100-33L,QFNFC40P400X400X100-33M; Last Time Buy: N/A; Lead Time: N/A; MPN: CC13XX 4X4; MPN Status: ACTIVE; MSL: N/A; MTBF: N/A; MTBF Standard: N/A; Manufacturer: TEXAS INSTRUMENTS; Max Oper Temp: N/A; Min Oper Temp: N/A; Mounting Type: SMD; NOTE Status: PREFERRED; Old Footprint: QFNFC40P400X400X100-33N; PCB Package: QFN32; Packing Size: N/A; Packing Type: N/A; Part Number: 18-28963; Part Type: IC\ANALOG\OTHER; Revision: R001; RoHS Status: PART NOT KNOWN; Rtd Voltage: N/A; WEIGHT: N/A
Y1 = CRYSTAL: CRYSTAL, RESONATOR, 32.768kHz, -20PPM/+20PPM, -40DEGC/+85DEGC, SMD; ALT_SYMBOLS: XTAL_FC-135L,XTAL_FC-135M; AutoDoc File: http://notefied-dynamic-precision.com/DB/Apps/Desktop/Item/Object.aspx?id=91966; Budget Currency: USD; Budget Price: 1.25375; Capacitance: 7pF; Datasheet URL 1: http://www.eea.epson.com/portal/pls/portal/docs/1/1525528.PDF; Datasheet URL 2: http://www.eea.epson.com/portal/pls/portal/docs/1/1525451.PDF; Definied Quality: INDUSTRIAL; Esd Level: N/A; FPLIST: XTAL_FC-135N,XTAL_FC-135L,XTAL_FC-135M; Last Time Buy: N/A; Lead Time: 10; MPN: FC-135 32.7680KA-AG0; MPN Status: ACTIVE; MSL: N/A; MTBF: N/A; MTBF Standard: N/A; Manufacturer: EPSON; Max Oper Temp: +85DEGC; Max Tol: +20PPM; Min Oper Temp: -40DEGC; Min Tol: -20PPM; Mounting Type: SMD; NOTE Status: PREFERRED; Packing Size: 1000; Packing Type: TAPE_&_REEL; Part Number: 12-00546; Part Type: CRYSTAL\OSCILLATOR\MEMS; Revision: R001; RoHS Status: ROHS_COMPLIANT; WEIGHT: N/A
Y2 = XTAL_TSX_3225_V1: CRYSTAL, OSCILATOR, 24MHz, -40DEGC/+85DEGC, SMD; ALT_SYMBOLS: OSCCC250X320X80-4L,OSCCC250X320X80-4M; AutoDoc File: http://notefied-dynamic-precision.com/DB/Apps/Desktop/Item/Object.aspx?id=85182; Budget Currency: N/A; Budget Price: N/A; Capacitance: 7pF; Datasheet URL 1: N/A; Datasheet URL 2: http://www.eea.epson.com/portal/pls/portal/docs/1/1529476.PDF; Definied Quality: INDUSTRIAL; Esd Level: N/A; FPLIST: OSCCC250X320X80-4N,OSCCC250X320X80-4L,OSCCC250X320X80-4M; Last Time Buy: N/A; Lead Time: N/A; MPN: TSX-3225 24MHz; MPN Status: ACTIVE; MSL: N/A; MTBF: N/A; MTBF Standard: N/A; Manufacturer: EPSON; Max Oper Temp: +85DEGC; Min Oper Temp: -40DEGC; Mounting Type: SMD; NOTE Status: PREFERRED; Old Footprint: OSCCC250X320X80-4N; Packing Size: N/A; Packing Type: N/A; Part Number: 12-00419; Part Type: CRYSTAL\OSCILLATOR; Revision: R001; RoHS Status: ROHS_COMPLIANT; WEIGHT: N/A

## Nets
GND: C3.2 C4.2 C5.2 C6.2 C8.2 C9.2 C11.1 C12.2 C13.1 C14.1 C17.2 C18.2 C19.2 C20.2 C21.2 C23.2 C24.2 C25.2 J1.2 J1.3 J1.4 J1.5 L15.2 P1.1 P1.19 P2.2 P2.20 U1.3(VSS) U1.7(VSS) U1.17(VSS) U1.20(VSS) U1.29(VSS) U1.33(EGP) Y2.2 Y2.4
VDD_EB: FL1.2 P2.7 P2.9
VDDR: C8.1 C9.1 C23.1 L1.2 U1.28(VDDR) U1.32(VDDR)
VDDS: C3.1 C4.1 C5.1 C6.1 FL1.1 R1.2 U1.11(VDDS2) U1.19(VDDS_DCDC) U1.27(VDDS)
DCDC_SW: L1.1 U1.18(DCDC_SW)
DIO_0: P1.20 U1.8(DIO_0)
DIO_1: P1.7 U1.9(DIO_1)
DIO_2: P1.9 U1.10(DIO_2)
DIO_3: P1.12 R6.1
DIO_3/JTAG_TDO: R4.1 R6.2 U1.15(DIO_3)
DIO_4: P1.10 R5.1
DIO_4/JTAG_TDI: R3.1 R5.2 U1.16(DIO_4)
DIO_5 : P1.2 U1.22(DIO_5)
DIO_6 : P1.4 U1.23(DIO_6)
DIO_7: P1.14 U1.24(DIO_7)
DIO_8: P1.16 U1.25(DIO_8)
DIO_9: P1.18 U1.26(DIO_9)
JTAG_TCK: P2.1 U1.14(JTAG_TCKC)
JTAG_TDI: P2.17 R3.2
JTAG_TDO: P2.19 R4.2
JTAG_TMS: P2.4 U1.13(JTAG_TMSC)
nRESET: C20.1 P2.15 R1.1 U1.21(RESET_N)
N309359: C19.1 U1.12(DCOUPL)
N310061: C24.1 U1.31(X24M_N) Y2.3
N310119: C25.1 U1.30(X24M_P) Y2.1
N320943: C17.1 U1.5(X32K_Q1) Y1.1
N320947: C18.1 U1.6(X32K_Q2) Y1.2
N473699: C14.2 C15.2 C16.2 L14.2
N473851: C15.1 J1.1
N473855: C11.2 L11.2 L12.1 U1.1(RF_P)
N473863: C22.1 L11.1 L21.2 U1.2(RF_N)
N473875: C12.1 C22.2 L12.2 L13.1
N473891: C13.2 L13.2 L14.1
N473923: A1.1(FEED/GND) L15.1 R2.2
N474143: C16.1 R2.1
N475793: C21.1 L21.1 U1.4(RX/TX)

Not connected (* = marked no-connect by the designer): FIDU1 1*; FIDU2 1*; FIDU3 1*; FIDU4 1*; FIDU5 1*; FIDU6 1*; P1 3* 5* 6* 8* 11 13 15 17; P2 3* 5* 6* 8* 10* 11* 12* 13* 14* 16* 18*

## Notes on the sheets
sheet 1
- VDDS Decoupling Capacitors
- VDDR Decoupling Capacitors
- Pin 11
- Pin 27
- Pin 19
- Pin 28
- Place L1 and
  C8 close to pin 18
- Mount either C15 or C16
  To select SMA or PCB ant.
- EM connector 1
- EM connector 2
sheet 2
- 0.1.0  Initial revision
  ---------------------------------------------------------------------------------------------
  0.1.1 Changed L11 from 27nH to 22nH
        Changed L12 and L21 from 7.5nH to 8.2nH
        Changed C11 and C22 from 3.6pF to 3.3pF
  ---------------------------------------------------------------------------------------------
  1.0.0 Revision number update for web
